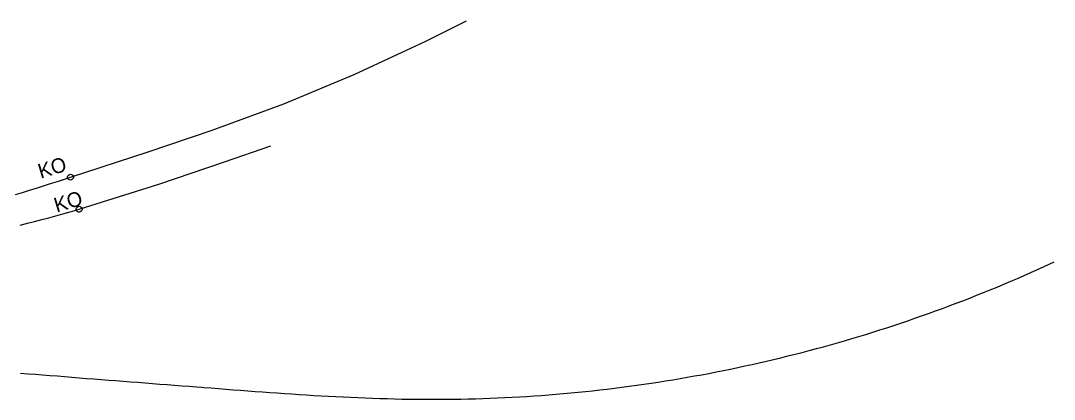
# Model space of a CAD drawing. Extents: x -669628 to -669207, y -977198 to -977075.
# Drawn here: x -669347.9 to -669207.3, y -977153.8 to -977102.4 of the extents above; entities that cross this region are included whole.
import ezdxf

# ---------------------------------------------------------------- set-up
doc = ezdxf.new("R2010")
doc.units = 0
for name, color, linetype in [('Navazující stavba', 7, 'Continuous'), ('SO 11-10-01', 7, 'Continuous'), ('Stávající', 7, 'Continuous')]:
    doc.layers.add(name, color=color, linetype=linetype)

msp = doc.modelspace()

# ---------------------------------------------------------------- linework, layer by layer
at = {"layer": 'Navazující stavba'}
for points in [[(-669290.76, -977153.84), (-669290.05, -977153.83), (-669289.05, -977153.82), (-669288.05, -977153.81), (-669287.05, -977153.79), (-669286.05, -977153.76), (-669285.06, -977153.73), (-669284.06, -977153.69), (-669283.06, -977153.65), (-669282.06, -977153.61), (-669281.06, -977153.56), (-669280.06, -977153.5), (-669279.06, -977153.44), (-669278.06, -977153.37), (-669277.07, -977153.3), (-669276.07, -977153.23), (-669275.07, -977153.15), (-669274.08, -977153.06), (-669273.08, -977152.97), (-669272.09, -977152.88), (-669271.09, -977152.77), (-669270.1, -977152.67), (-669269.1, -977152.56), (-669268.11, -977152.44), (-669267.12, -977152.32), (-669266.12, -977152.2), (-669265.13, -977152.07), (-669264.14, -977151.93), (-669263.15, -977151.79), (-669262.16, -977151.65), (-669261.17, -977151.5), (-669260.19, -977151.34), (-669259.2, -977151.18), (-669258.21, -977151.01), (-669257.23, -977150.84), (-669256.24, -977150.67), (-669255.26, -977150.49), (-669254.28, -977150.31), (-669253.29, -977150.12), (-669252.31, -977149.92), (-669251.33, -977149.72), (-669250.35, -977149.52), (-669249.38, -977149.31), (-669248.4, -977149.09), (-669247.42, -977148.88), (-669246.45, -977148.65), (-669245.48, -977148.42), (-669244.5, -977148.19), (-669243.53, -977147.95), (-669242.56, -977147.71), (-669241.59, -977147.46), (-669240.63, -977147.21), (-669239.66, -977146.95), (-669238.7, -977146.69), (-669237.73, -977146.42), (-669236.77, -977146.15), (-669235.81, -977145.87), (-669234.85, -977145.59), (-669233.89, -977145.3), (-669232.93, -977145.01), (-669231.98, -977144.71), (-669231.03, -977144.41), (-669230.07, -977144.1), (-669229.12, -977143.79), (-669228.17, -977143.48), (-669227.23, -977143.16), (-669226.28, -977142.83), (-669225.34, -977142.5), (-669224.39, -977142.17), (-669223.45, -977141.83), (-669222.51, -977141.49), (-669221.58, -977141.14), (-669220.64, -977140.79), (-669219.71, -977140.43), (-669218.78, -977140.07), (-669217.85, -977139.7), (-669216.92, -977139.33), (-669215.99, -977138.95), (-669215.07, -977138.57), (-669214.14, -977138.18), (-669213.22, -977137.79), (-669212.3, -977137.4), (-669211.39, -977137), (-669210.47, -977136.6), (-669209.56, -977136.19), (-669208.65, -977135.78), (-669207.28, -977135.15)], [(-669347.93, -977150.29), (-669346.93, -977150.36), (-669345.93, -977150.44), (-669344.94, -977150.52), (-669343.94, -977150.6), (-669342.94, -977150.67), (-669341.95, -977150.75), (-669340.95, -977150.83), (-669339.95, -977150.91), (-669338.96, -977150.99), (-669337.96, -977151.06), (-669336.96, -977151.14), (-669335.96, -977151.22), (-669334.97, -977151.3), (-669333.97, -977151.37), (-669332.97, -977151.45), (-669331.98, -977151.53), (-669330.98, -977151.61), (-669329.98, -977151.68), (-669328.99, -977151.76), (-669327.99, -977151.84), (-669326.99, -977151.92), (-669325.99, -977151.99), (-669325, -977152.07), (-669324, -977152.15), (-669323.3, -977152.2), (-669323, -977152.23), (-669322.01, -977152.3), (-669321.03, -977152.38), (-669321.01, -977152.38), (-669320.01, -977152.46), (-669319.02, -977152.54), (-669318.02, -977152.61), (-669317.02, -977152.69), (-669316.02, -977152.76), (-669315.03, -977152.83), (-669314.03, -977152.9), (-669313.03, -977152.97), (-669312.03, -977153.04), (-669311.04, -977153.11), (-669310.04, -977153.18), (-669309.04, -977153.24), (-669308.04, -977153.3), (-669307.04, -977153.36), (-669306.05, -977153.41), (-669305.05, -977153.47), (-669304.05, -977153.52), (-669303.05, -977153.56), (-669302.05, -977153.61), (-669301.05, -977153.65), (-669300.05, -977153.69), (-669299.05, -977153.72), (-669298.05, -977153.75), (-669297.05, -977153.77), (-669296.05, -977153.8), (-669295.05, -977153.81), (-669294.05, -977153.83), (-669293.05, -977153.84), (-669292.05, -977153.84), (-669291.15, -977153.84), (-669291.05, -977153.84), (-669290.76, -977153.84)]]:
    msp.add_lwpolyline(points, dxfattribs=at)
at = {"layer": 'SO 11-10-01'}
for p, q in [((-669342.92, -977124.21), (-669341.96, -977123.9)), ((-669341.96, -977123.9), (-669341.15, -977123.64)), ((-669346.73, -977125.42), (-669345.77, -977125.12)), ((-669345.77, -977125.12), (-669344.82, -977124.82)), ((-669344.82, -977124.82), (-669343.87, -977124.51)), ((-669343.87, -977124.51), (-669342.92, -977124.21)), ((-669348.64, -977126.01), (-669347.68, -977125.71)), ((-669347.68, -977125.71), (-669346.73, -977125.42)), ((-669341.21, -977128.35), (-669340.25, -977128.08)), ((-669340.25, -977128.08), (-669339.98, -977128)), ((-669346.04, -977129.66), (-669345.07, -977129.4)), ((-669345.07, -977129.4), (-669344.11, -977129.15)), ((-669344.11, -977129.15), (-669343.14, -977128.88)), ((-669343.14, -977128.88), (-669342.18, -977128.62)), ((-669342.18, -977128.62), (-669341.21, -977128.35)), ((-669347.98, -977130.16), (-669347.01, -977129.91)), ((-669347.01, -977129.91), (-669346.04, -977129.66))]:
    msp.add_line(p, q, dxfattribs=at)
for points in [[(-669341.14, -977124.04), (-669341.27, -977124.01), (-669341.41, -977123.94), (-669341.49, -977123.86), (-669341.55, -977123.73), (-669341.55, -977123.57), (-669341.5, -977123.46), (-669341.43, -977123.35), (-669341.3, -977123.27), (-669341.17, -977123.24), (-669341.03, -977123.26), (-669340.9, -977123.33), (-669340.81, -977123.41), (-669340.75, -977123.54), (-669340.75, -977123.7), (-669340.8, -977123.81), (-669340.88, -977123.92), (-669341.01, -977124), (-669341.14, -977124.04)], [(-669341.14, -977124.04), (-669341.27, -977124.01), (-669341.41, -977123.94), (-669341.49, -977123.86), (-669341.55, -977123.73), (-669341.55, -977123.57), (-669341.5, -977123.46), (-669341.43, -977123.35), (-669341.3, -977123.27), (-669341.17, -977123.24), (-669341.03, -977123.26), (-669340.9, -977123.33), (-669340.81, -977123.41), (-669340.75, -977123.54), (-669340.75, -977123.7), (-669340.8, -977123.81), (-669340.88, -977123.92), (-669341.01, -977124), (-669341.14, -977124.04)], [(-669339.96, -977128.4), (-669340.1, -977128.38), (-669340.23, -977128.3), (-669340.31, -977128.22), (-669340.37, -977128.09), (-669340.38, -977127.93), (-669340.33, -977127.82), (-669340.25, -977127.72), (-669340.12, -977127.63), (-669339.99, -977127.6), (-669339.85, -977127.62), (-669339.72, -977127.7), (-669339.64, -977127.78), (-669339.58, -977127.91), (-669339.57, -977128.07), (-669339.62, -977128.18), (-669339.7, -977128.28), (-669339.83, -977128.37), (-669339.96, -977128.4)]]:
    msp.add_lwpolyline(points, dxfattribs=at)
at = {"layer": 'Stávající'}
for points in [[(-669341.15, -977123.64), (-669341.15, -977123.64), (-669330.59, -977120.17), (-669321.89, -977117.26), (-669312.13, -977113.67), (-669302.53, -977109.66), (-669292.78, -977105.14), (-669287.25, -977102.36)], [(-669339.98, -977128), (-669339.98, -977128), (-669329.14, -977124.61), (-669320.21, -977121.55), (-669313.89, -977119.38)]]:
    msp.add_lwpolyline(points, dxfattribs=at)

# ---------------------------------------------------------------- texts
at = {"layer": 'SO 11-10-01'}
for p in [(-669345.21, -977123.85), (-669343.03, -977128.47)]:
    msp.add_text('KO', height=2, rotation=16.9214, dxfattribs=at).set_placement(p)

doc.saveas('drawing.dxf')
